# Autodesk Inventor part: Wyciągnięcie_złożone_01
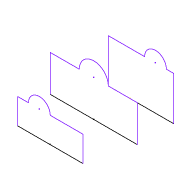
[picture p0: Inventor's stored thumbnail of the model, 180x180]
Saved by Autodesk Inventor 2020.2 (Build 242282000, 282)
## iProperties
Created: 2015-03
Part Number: Wyciągnięcie_złożone_01
Material: Ogólny
Document SubType Name: Modeling
Designer: F.Stasiak
Density: 1 g/cm^3
Appearance: Domyślna
Manager: www.cadconsulting.pl
Company: Fabian Stasiak CAD Consulting
Author: F.Stasiak
Subject: Zbiór ćwiczeń. Autodesk Inventor 2020. Kurs podstawowy
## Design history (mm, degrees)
node "Płaszczyzna konstrukcyjna1"
node "Płaszczyzna konstrukcyjna2"
sketch "Szkic1"
  geometry: L1 (-60, 0)-(60, 0); L2 (60, 0)-(60, 50); L3 (-60, 50)-(-60, 0); L4 (60, 50)-(20, 50); L5 (-20, 50)-(-60, 50); A1 r 20 centre (0, 50) between (20, 50) and (-20, 50); 2 further points
  constraints: 10 end point, 3 parallel, 2 collinear, 2 point on circle, 1 centre point, 1 coincident, 1 horizontal, 1 midpoint, 1 perpendicular, 1 point on line
sketch "Szkic2"
  geometry: L1 (45, 35)-(45, 0); L2 (45, 0)-(-45, 0); L3 (-45, 0)-(-45, 35); L4 (-45, 35)-(-30, 35); L5 (0, 35)-(45, 35); A1 r 15 centre (-15, 35) between (0, 35) and (-30, 35); 2 further points
  constraints: 10 end point, 3 parallel, 2 horizontal, 2 perpendicular, 2 point on circle, 1 centre point, 1 coincident, 1 collinear, 1 midpoint, 1 point on line
sketch "Szkic3"
  geometry: L1 (-30, 0)-(60, 0); L2 (60, 0)-(60, 60); L3 (-30, 60)-(-30, 0); L4 (60, 60)-(50, 60); L5 (20, 60)-(-30, 60); A1 r 15 centre (35, 60) between (50, 60) and (20, 60); 1 further point
  constraints: 10 end point, 3 parallel, 2 point on circle, 2 point on line, 1 centre point, 1 collinear, 1 horizontal, 1 perpendicular
